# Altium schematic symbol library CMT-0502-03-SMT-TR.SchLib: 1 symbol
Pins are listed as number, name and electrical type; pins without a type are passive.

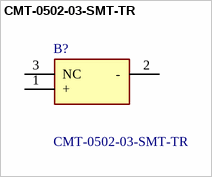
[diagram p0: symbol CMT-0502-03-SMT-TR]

## CMT-0502-03-SMT-TR
designator B?
CMT-0502-03-SMT-TR - 5 mm, 3 Vo-p, 75 dB, Surface Mount, Magnetic Audio Transducer Buzzer; Manufacturer_Name: Same Sky; Geometry.Height: 2.3mm
footprint CMT050203SMTTR
pins: 1 +, 2 -, 3 NC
